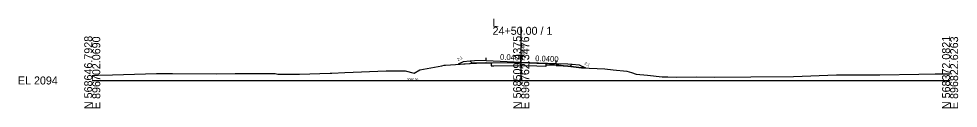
# Model space of a CAD drawing. Extents: x -26 to 1603, y -10 to 13527.
# Drawn here: x -25.7 to 302.8, y 11990.3 to 12021.6 of the extents above; entities that cross this region are included whole.
import ezdxf

# ---------------------------------------------------------------- set-up
doc = ezdxf.new("R2010")
doc.units = 0
for name, color, linetype in [('Default', 7, 'Continuous'), ('Exist XS Center Line Elevation Label', 7, 'Continuous'), ('Exist XS Ground Line', 7, 'Continuous'), ('Old_Level_61', 7, 'Continuous'), ('Old_Level_63', 7, 'Continuous'), ('Prop XS Ditch Standard Text', 7, 'Continuous'), ('Prop XS Earthwork Shape', 7, 'Continuous'), ('Prop XS EOT Tick Mark', 7, 'Continuous'), ('Prop XS Finish Grade', 7, 'Continuous'), ('Prop XS Finish Grade Earthwork', 7, 'Continuous'), ('Prop XS Finish Grade Paved Shoulder', 7, 'Continuous'), ('Prop XS Finish Grade Pavement', 7, 'Continuous'), ('Prop XS Side Slope Text', 7, 'Continuous'), ('Prop XS Subgrade Earthwork', 7, 'Continuous'), ('Prop XSC Text', 7, 'Continuous')]:
    doc.layers.add(name, color=color, linetype=linetype)

msp = doc.modelspace()

# ---------------------------------------------------------------- linework, layer by layer
at = {"layer": 'Exist XS Ground Line'}
for p, q in [((114.56, 12003.72), (122.29, 12005.16)), ((122.29, 12005.16), (123.07, 12005.33)), ((123.07, 12005.33), (123.58, 12005.4)), ((123.58, 12005.4), (133.9, 12006.07)), ((133.9, 12006.07), (135.95, 12006.18)), ((135.95, 12006.18), (139.48, 12006.14)), ((139.48, 12006.14), (139.9, 12006.14)), ((139.9, 12006.14), (149.64, 12006.26)), ((149.64, 12006.26), (150, 12006.24)), ((150, 12006.24), (155.5, 12006.07)), ((155.5, 12006.07), (158.57, 12005.98)), ((158.57, 12005.98), (159.04, 12005.92)), ((159.04, 12005.92), (161.71, 12005.56)), ((161.71, 12005.56), (163.19, 12005.42)), ((163.19, 12005.42), (167.34, 12004.89)), ((167.34, 12004.89), (171.09, 12004.47)), ((0, 12001.75), (2.04, 12001.82)), ((2.04, 12001.82), (7.13, 12001.98)), ((7.13, 12001.98), (22.42, 12002.4)), ((22.42, 12002.4), (26.35, 12002.46)), ((26.35, 12002.46), (28.09, 12002.48)), ((28.09, 12002.48), (43.55, 12002.35)), ((43.55, 12002.35), (49.99, 12002.44)), ((49.99, 12002.44), (63.99, 12002.46)), ((63.99, 12002.46), (64.89, 12002.26)), ((64.89, 12002.26), (72.49, 12002.21)), ((72.49, 12002.21), (83.2, 12002.55)), ((83.2, 12002.55), (83.74, 12002.56)), ((83.74, 12002.56), (88.35, 12002.76)), ((88.35, 12002.76), (102.78, 12003.36)), ((102.78, 12003.36), (109.47, 12003.37)), ((109.47, 12003.37), (112.56, 12002.56)), ((112.56, 12002.56), (114.56, 12003.72)), ((171.09, 12004.47), (179.27, 12004.1)), ((179.27, 12004.1), (182.16, 12003.78)), ((182.16, 12003.78), (186.91, 12003.24)), ((186.91, 12003.24), (188.53, 12002.75)), ((188.53, 12002.75), (190.22, 12002.25)), ((190.22, 12002.25), (194.22, 12001.87)), ((194.22, 12001.87), (199.3, 12001.31)), ((199.3, 12001.31), (201.27, 12001.27)), ((217.55, 12001.19), (230.28, 12001.3)), ((230.28, 12001.3), (245.19, 12001.37)), ((245.19, 12001.37), (260.24, 12001.94)), ((260.24, 12001.94), (262.2, 12002.03)), ((262.2, 12002.03), (275.44, 12002.01)), ((275.44, 12002.01), (289.04, 12002.25)), ((289.04, 12002.25), (294.73, 12002.31)), ((294.73, 12002.31), (295.85, 12002.35)), ((295.85, 12002.35), (300, 12002.34)), ((201.27, 12001.27), (204.44, 12001.17)), ((204.44, 12001.17), (211.44, 12001.27)), ((211.44, 12001.27), (217.55, 12001.19))]:
    msp.add_line(p, q, dxfattribs=at)
at = {"layer": 'Old_Level_61'}
for p, q in [((139.48, 12006.14), (139.48, 12005.14)), ((139.48, 12005.14), (139.9, 12005.14)), ((139.9, 12005.14), (140.48, 12005.15)), ((140.48, 12005.15), (149.64, 12005.26)), ((149.64, 12005.26), (150, 12005.24)), ((150, 12005.24), (155.5, 12005.07)), ((155.5, 12005.07), (158.57, 12004.98)), ((158.57, 12004.98), (158.7, 12004.96)), ((158.7, 12004.96), (158.7, 12005.96))]:
    msp.add_line(p, q, dxfattribs=at)
at = {"layer": 'Old_Level_63'}
for p, q in [((150, 12000), (150, 12018.77)), ((0, 12000), (150, 12000)), ((150, 12000), (300, 12000))]:
    msp.add_line(p, q, dxfattribs=at)
at = {"layer": 'Prop XS Earthwork Shape'}
for points in [[(132.21, 12006.75), (129.71, 12006.55), (127.97, 12005.68), (133.9, 12006.07), (134.35, 12006.09), (132.9, 12006.06)], [(137.64, 12006.16), (134.35, 12006.09), (135.95, 12006.18)], [(137.64, 12006.16), (137.8, 12006.16), (137.72, 12006.16)], [(137.8, 12006.16), (139.48, 12006.14), (139.48, 12006.09)], [(158.7, 12005.32), (158.7, 12005.96), (159.04, 12005.92), (161.71, 12005.56), (163.19, 12005.42), (166.37, 12005.01), (162.28, 12005.18)], [(170.29, 12005.49), (172.46, 12004.4), (171.09, 12004.47), (167.34, 12004.89), (166.37, 12005.01), (167.11, 12004.98), (167.82, 12005.69)]]:
    msp.add_lwpolyline(points, close=True, dxfattribs=at)
at = {"layer": 'Prop XS EOT Tick Mark'}
for p, q in [((137.72, 12006.95), (137.72, 12007.95)), ((162.28, 12005.97), (162.28, 12006.97))]:
    msp.add_line(p, q, dxfattribs=at)
at = {"layer": 'Prop XS Finish Grade'}
for p, q in [((133.71, 12006.87), (132.21, 12006.75)), ((166.29, 12005.81), (167.82, 12005.69))]:
    msp.add_line(p, q, dxfattribs=at)
at = {"layer": 'Prop XS Finish Grade Earthwork'}
for p, q in [((129.71, 12006.55), (127.97, 12005.68)), ((132.21, 12006.75), (129.71, 12006.55)), ((167.82, 12005.69), (170.29, 12005.49)), ((170.29, 12005.49), (172.46, 12004.4))]:
    msp.add_line(p, q, dxfattribs=at)
at = {"layer": 'Prop XS Finish Grade Paved Shoulder'}
for p, q in [((137.72, 12006.95), (133.71, 12006.87)), ((162.28, 12005.97), (166.29, 12005.81))]:
    msp.add_line(p, q, dxfattribs=at)
at = {"layer": 'Prop XS Finish Grade Pavement'}
for p, q in [((137.72, 12006.95), (150, 12006.46)), ((150, 12006.46), (162.28, 12005.97))]:
    msp.add_line(p, q, dxfattribs=at)
at = {"layer": 'Prop XS Subgrade Earthwork'}
for p, q in [((132.9, 12006.06), (132.21, 12006.75)), ((137.72, 12006.16), (132.9, 12006.06)), ((139.48, 12006.09), (137.72, 12006.16)), ((139.48, 12006.09), (139.48, 12006.14)), ((158.7, 12005.32), (158.7, 12005.96)), ((162.28, 12005.18), (158.7, 12005.32)), ((162.28, 12005.18), (167.11, 12004.98)), ((167.11, 12004.98), (167.82, 12005.69))]:
    msp.add_line(p, q, dxfattribs=at)

# ---------------------------------------------------------------- texts
at = {"layer": 'Default'}
for p in [(142.58, 12007.26), (154.86, 12006.77)]:
    msp.add_text('0.0400', height=2, rotation=357.7094, dxfattribs=at).set_placement(p)
at = {"layer": 'Exist XS Center Line Elevation Label'}
msp.add_text('2100.24', height=1, rotation=90, dxfattribs=at).set_placement((150.5, 11998.68))
at = {"layer": 'Old_Level_63'}
for s, p in [('L', (140, 12018.77)), ('24+50.00 / 1', (140, 12015.97)), ('EL 2094', (-26, 11998.6))]:
    msp.add_text(s, height=2.8, dxfattribs=at).set_placement(p)
for s, p in [('N 568646.7928', (0, 11990)), ('E 896702.0690', (2.8, 11990)), ('N 568509.4375', (150, 11990)), ('E 896762.3476', (152.8, 11990)), ('N 568372.0821', (300, 11990)), ('E 896822.6263', (302.8, 11990))]:
    msp.add_text(s, height=2.8, rotation=90, dxfattribs=at).set_placement(p)
at = {"layer": 'Prop XS Ditch Standard Text'}
msp.add_text('2096.56', height=0.8, dxfattribs=at).set_placement((110.04, 11999.93))
at = {"layer": 'Prop XS Side Slope Text'}
for rotation, p in [(26.565, (127.92, 12006.78)), (333.4349, (172.02, 12005.74))]:
    msp.add_text('2:1', height=1, rotation=rotation, dxfattribs=at).set_placement(p)
at = {"layer": 'Prop XSC Text'}
msp.add_text(' 2100.46', height=1.2, rotation=90, dxfattribs=at).set_placement((151.2, 12006.46))

doc.saveas('drawing.dxf')
